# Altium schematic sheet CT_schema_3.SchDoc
size 283 x 147 mm
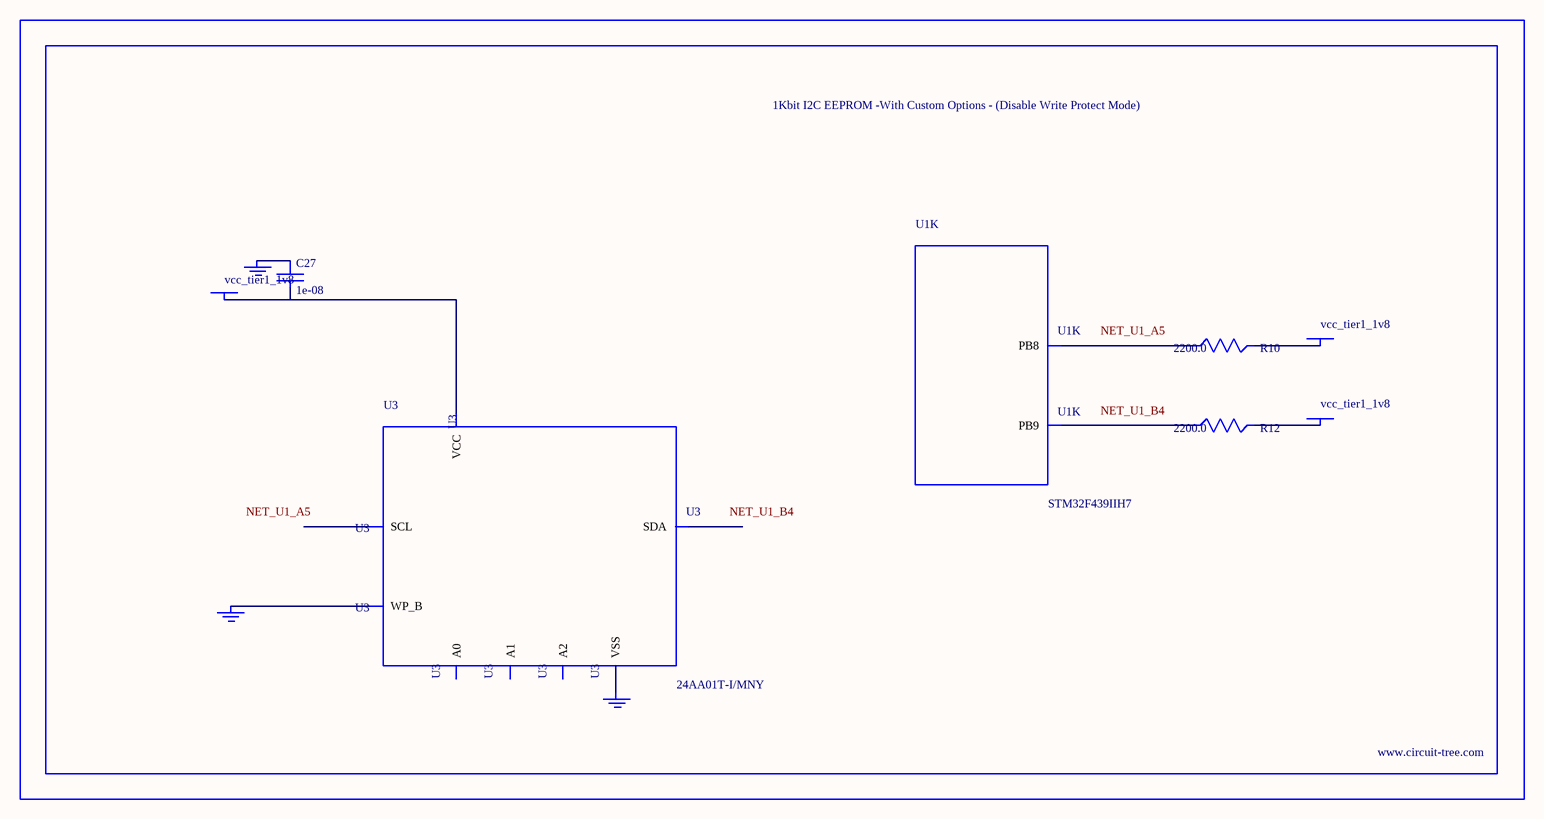
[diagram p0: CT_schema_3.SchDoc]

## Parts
BORDER2  (no value)
C27  1e-08  [C0402]
GND_INSTANCE_2_0  (no value)
GND_INSTANCE_2_1  (no value)
GND_INSTANCE_2_2  (no value)
POWER_INSTANCE_2_0  vcc_tier1_1v8
POWER_INSTANCE_2_1  vcc_tier1_1v8
POWER_INSTANCE_2_2  vcc_tier1_1v8
R10  2200.0  [R0603]
R12  2200.0  [R0603]
U1  STM32F439IIH7  [UFBGA176_25]  (part K of 14)
U3  24AA01T-I/MNY  [TDFN-8/6MM]

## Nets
NetC27_1: C27.1 GND_INSTANCE_2_1.0(GND)
NetC27_2: C27.2 POWER_INSTANCE_2_0.0(PWR) U3.8(VCC)
NetGND_INSTANCE_2_0_0: GND_INSTANCE_2_0.0(GND) U3.7(WP_B)
NetGND_INSTANCE_2_2_0: GND_INSTANCE_2_2.0(GND) U3.4(VSS)
NetPOWER_INSTANCE_2_1_0: POWER_INSTANCE_2_1.0(PWR) R10.2
NetPOWER_INSTANCE_2_2_0: POWER_INSTANCE_2_2.0(PWR) R12.2
NetR10_1: R10.1 U1.A5(PB8)
NetR12_1: R12.1 U1.B4(PB9)

Not connected (* = marked no-connect by the designer): U3 1(A0) 2(A1) 3(A2) 5(SDA) 6(SCL)

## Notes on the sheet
- Labels drawn without touching a wire or pin: NET_U1_A5, NET_U1_B4

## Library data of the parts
BORDER2 = BORDER_PAGE2
C27 = C0402C103K3RAC
GND_INSTANCE_2_0-GND_INSTANCE_2_2 = GND
POWER_INSTANCE_2_0-POWER_INSTANCE_2_2 = PWR
R10 R12 = RC0603JR-072K2L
